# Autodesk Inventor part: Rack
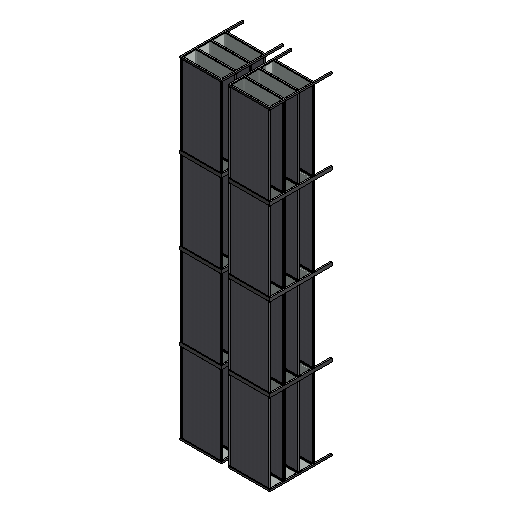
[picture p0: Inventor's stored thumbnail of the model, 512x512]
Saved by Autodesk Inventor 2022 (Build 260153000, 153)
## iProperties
RuleStatus: InUse
Created: 2009-09
Part Number: Rack
Document SubType Name: Modeling
Designer: Autodesk, Inc.
Density: 7.85 g/cm^3
Material: Steel
Mass: 1.60174e+06 g
Surface Area: 337911 cm^2
Volume: 204043 cm^3
Appearance: 陽極酸化 - 灰色 テクスチャ
Key Parameters: BaySpan=2400.000 mm;BayDepth=1200.000 mm;BayHeight=1800.000 mm;BeamNumber=4.000 ul;FlueDepth=200.000 mm;RowNumber=2.000 ul;ColumnNumber=4.000 ul;SupportHeight=5
Author: Autodesk, Inc.
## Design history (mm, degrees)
sketch "Sketch1"
  geometry: L1 (0, 1200)-(0, -1200); L2 (-600, -1200)-(600, -1200); L3 (600, -1200)-(600, -1150); L4 (600, -1150)-(-600, -1150); L5 (-600, -1150)-(-600, -1200); L6 (-600, -1150)-(-560, -1150); L7 (-560, -1150)-(-560, -1200); L8 (-560, -1200)-(-600, -1200); L9 (-600, -1200)-(-600, -1150); L10 (600, -1150)-(560, -1150); L11 (560, -1150)-(560, -1200); L12 (560, -1200)-(600, -1200); L13 (600, -1200)-(600, -1150); 2 further points
  constraints: 26 end point, 6 parallel, 3 horizontal, 3 perpendicular, 2 midpoint, 2 point on line, 1 coincident, 1 vertical
  dimensions: "d0" = 2400 distance of L1.start L1.end (derived); "d1" = 1200 distance of L2.start L2.end (derived); "d2" = 50 distance of L4.end L2.start; "d3" = 40 distance of L4.end L6.end; "d4" = 40 distance of L3.end L10.end
extrude "Extrusion1" new body sketch "Sketch1" distance "d5" = 500 (derived); taper "d6" = 0 deg
workplane "Work Plane1"
sketch "Sketch2"
  geometry: L1 (-560, -1150)-(-560, -1200) reference; L2 (-600, -1150)-(-560, -1150) reference; L3 (-600, -1200)-(-600, -1150) reference; L4 (-560, -1200)-(-600, -1200) reference; L5 (600, -1150)-(600, -1200) reference; L6 (560, -1150)-(600, -1150) reference; L7 (560, -1200)-(560, -1150) reference; L8 (600, -1200)-(560, -1200) reference; L9 (-600, -1150)-(600, -1150); L10 (600, -1150)-(600, -1200); L11 (600, -1200)-(-600, -1200); L12 (-600, -1200)-(-600, -1150); 1 further point
  constraints: 8 end point, 2 parallel, 1 horizontal, 1 perpendicular
extrude "Extrusion2" join sketch "Sketch2" distance "d8" = 40; taper "d9" = 0 deg
sketch "Sketch3"
  geometry: L1 (-560, -1150)-(-560, -1200) reference; L2 (-600, -1150)-(-560, -1150) reference; L3 (-600, -1200)-(-600, -1150) reference; L4 (-560, -1200)-(-600, -1200) reference; L5 (600, -1150)-(560, -1150) reference; L6 (600, -1200)-(600, -1150) reference; L7 (560, -1200)-(600, -1200) reference; L8 (560, -1150)-(560, -1200) reference; 1 further point
extrude "Extrusion3" join sketch "Sketch3" distance "d10" = 1260 (derived); taper "d11" = 0 deg
sketch "Sketch4"
  geometry: L1 (-1760, 0)-(-1760, 50) reference; L2 (-1760, 20)-(-500, 20); L3 (-500, 20)-(-500, 30); L4 (-500, 30)-(-1760, 30); L5 (-1760, 30)-(-1760, 20); 2 further points
  constraints: 8 end point, 2 midpoint, 2 parallel, 1 horizontal, 1 perpendicular, 1 point on line
  dimensions: "d12" = 1260 distance of L2.start L2.end (derived); "d13" = 10 distance of L4.end L2.start
extrude "Extrusion4" join sketch "Sketch4" stored distance "d14" = 1260 (derived); taper "d15" = 0 deg
pattern_linear "Rectangular Pattern1" dims "d18" = 1260 (derived)
mirror "Mirror1"
sketch "Sketch5"
  geometry: L1 (0, 1800)-(0, 0) reference; L2 (1200, 0)-(0, 0) reference; L3 (1200, 1800)-(1200, 0) reference; L4 (1150, 15)-(50, 15); L5 (50, 15)-(50, 25); L6 (50, 25)-(1150, 25); L7 (1150, 25)-(1150, 15); 1 further point
  constraints: 8 end point, 2 parallel, 1 horizontal, 1 perpendicular
  dimensions: "d19" = 10 distance of L6.end L4.start; "d20" = 15 distance between parallel lines of L2 L4; "d21" = 50 distance between parallel lines of L3 L7; "d22" = 50 distance between parallel lines of L1 L5
extrude "Extrusion5" join sketch "Sketch5" stored distance "d23" = 1260 (derived); taper "d24" = 0 deg
sketch "Sketch6"
  geometry: L1 (0, 2300)-(10, 2300) reference; L2 (0, 0)-(0, 2300) reference; L3 (10, 0)-(0, 0) reference; L4 (-10, 0)-(20, 0); L5 (20, 0)-(20, 20); L6 (20, 20)-(-10, 20); L7 (-10, 20)-(-10, 0); L8 (-10, 2280)-(20, 2280); L9 (20, 2280)-(20, 2300); L10 (20, 2300)-(-10, 2300); L11 (-10, 2300)-(-10, 2280); L12 (-5, 20)-(15, 20); L13 (15, 20)-(15, 2280); L14 (15, 2280)-(-5, 2280); L15 (-5, 2280)-(-5, 20); 4 further points
  constraints: 24 end point, 6 midpoint, 6 parallel, 3 horizontal, 3 perpendicular, 2 collinear, 2 point on line
  dimensions: "d34" = 10 distance between parallel lines of L2 L7; "d35" = 20 distance of L6.end L4.start; "d36" = 5 distance between parallel lines of L15 L2
extrude "Extrusion6" join sketch "Sketch6" distance "d37" = 48; taper "d38" = 0 deg
mirror "Mirror2"
pattern_linear "Rectangular Pattern2" dims "d27" = 1260 (derived)
pattern_linear "Rectangular Pattern3"
pattern_linear "Rectangular Pattern4"
workpoint "Work Point1"
node "Landing Surface"
node "Insertion Point1"
body "Solid1"
sketch "Sketch7"
  geometry: L1 (-600, -1150)-(-560, -1150) reference; L2 (-600, -1200)-(-600, -1150) reference; L3 (-560, -1200)-(-600, -1200) reference; L4 (-560, -1150)-(-560, -1200) reference; L5 (-600, -1200)-(2000, -1200); L6 (2000, -1200)-(2000, 8400); L7 (2000, 8400)-(-600, 8400); L8 (-600, 8400)-(-600, -1200); L9 (-600, -1200)-(2000, 8400); L10 (-600, 8400)-(2000, -1200); 2 further points
  constraints: 12 end point, 2 parallel, 1 horizontal, 1 midpoint, 1 perpendicular
  dimensions: "d39" = 9600 distance of L7.end L2.start (derived); "d40" = 2600 distance of L6.end L7.end (derived)
node "Projected Loop1"
node "Projected Loop2"
node "Projected Loop3"
